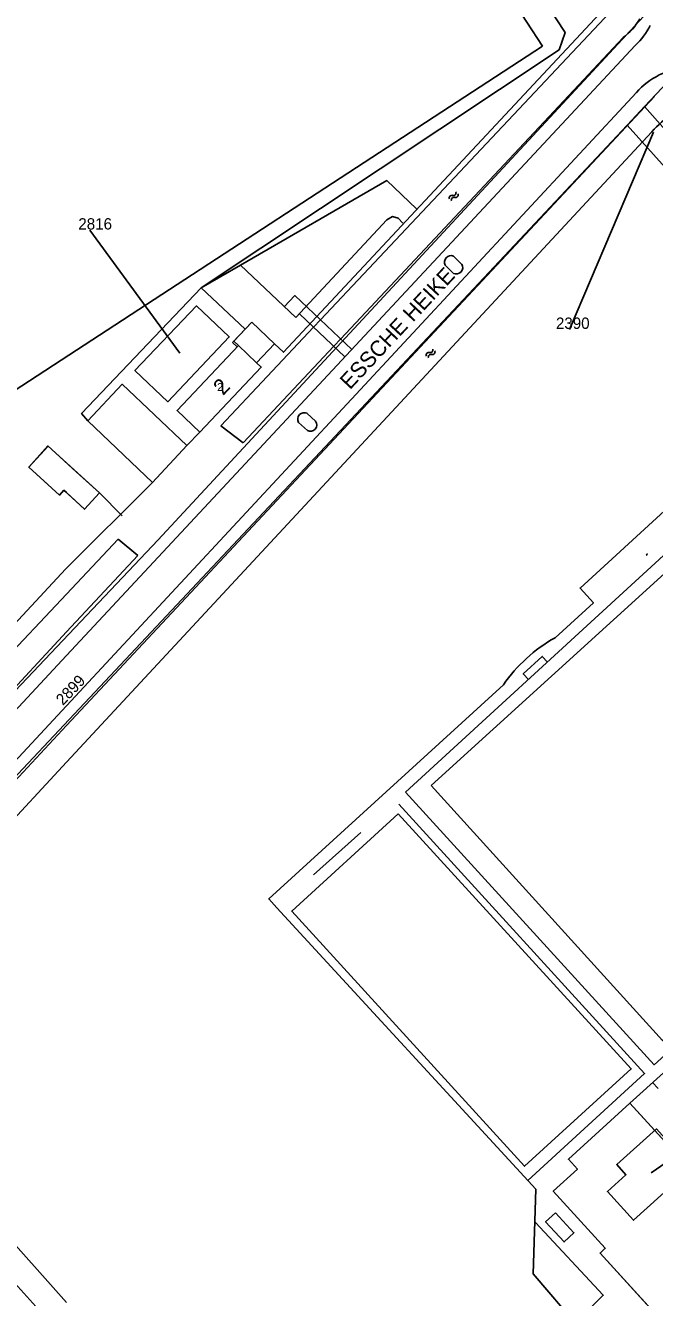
# Model space of a CAD drawing. Extents: x 148816 to 151297, y 399515 to 402500.
# Drawn here: x 149493.5 to 149593.5, y 401012.1 to 401214.2 of the extents above; entities that cross this region are included whole.
import ezdxf

# ---------------------------------------------------------------- set-up
doc = ezdxf.new("R2010")
doc.units = 0
for name, color, linetype in [('B01 Hoofdgebouw  [T] Norm', 7, 'Continuous'), ('B01 hoofgebouw', 7, 'Continuous'), ('B02 Bijgebouw  [D] Norm', 7, 'Continuous'), ('B03 Overig opstal  [D] Norm', 7, 'Continuous'), ('B03 Overig opstal  [T] Norm', 7, 'Continuous'), ('G01 perceelsgrens', 7, 'Continuous'), ('S02 Open verharding  Norm', 7, 'Continuous'), ('S05 Water  Norm', 7, 'Continuous'), ('T03 Hek raster  [D] Gem', 7, 'Continuous'), ('T03 Hek raster  [T] Norm', 7, 'Continuous'), ('T04 Haag heg  [D] Gem', 7, 'Continuous'), ('T09 Insteek water  [T] Norm', 7, 'Continuous'), ('T10 Cultuurscheiding  [T] Gem', 7, 'Continuous'), ('V00 Kant verharding algemeen  [T] Norm', 7, 'Continuous'), ('V00 Kant verharding algemeen secundair  [T] Gem', 7, 'Continuous'), ('Z01 perceelnummer', 7, 'Continuous'), ('Z02 huisnummer', 7, 'Continuous'), ('Z02 Huisnummer  [Tekst] Norm', 7, 'Continuous'), ('Z06 straatnaam', 7, 'Continuous')]:
    doc.layers.add(name, color=color, linetype=linetype)

msp = doc.modelspace()

# ---------------------------------------------------------------- linework, layer by layer
at = {"layer": 'B01 Hoofdgebouw  [T] Norm'}
for p, q in [((149510.87, 401159.36), (149520.65, 401169.63)), ((149520.65, 401169.63), (149525.85, 401164.7)), ((149525.85, 401164.7), (149516.11, 401154.4)), ((149517.57, 401153.03), (149527.31, 401163.33)), ((149527.31, 401163.33), (149530.21, 401160.58)), ((149516.11, 401154.4), (149510.87, 401159.36)), ((149530.94, 401159.89), (149521.2, 401149.59)), ((149530.21, 401160.58), (149530.94, 401159.89)), ((149503.37, 401151.34), (149508.83, 401157.18)), ((149508.83, 401157.18), (149519.14, 401147.42)), ((149521.2, 401149.59), (149517.57, 401153.03)), ((149513.64, 401141.57), (149503.37, 401151.34)), ((149505.23, 401139.91), (149497.07, 401147.36)), ((149519.14, 401147.42), (149513.64, 401141.57)), ((149494.02, 401144), (149498.88, 401139.58)), ((149498.88, 401139.58), (149499.58, 401140.35)), ((149499.58, 401140.35), (149500, 401139.96)), ((149500, 401139.96), (149502.86, 401137.31)), ((149502.86, 401137.31), (149505.23, 401139.91)), ((149589.53, 401042.97), (149579.77, 401034.06)), ((149599.61, 401031.96), (149589.53, 401042.97)), ((149579.77, 401034.06), (149581.2, 401032.49)), ((149581.2, 401032.49), (149577.36, 401028.99)), ((149577.36, 401028.99), (149585.63, 401019.93)), ((149585.63, 401019.93), (149584.79, 401019.16)), ((149584.79, 401019.16), (149601.71, 401000.62))]:
    msp.add_line(p, q, dxfattribs=at)
at = {"layer": 'B01 hoofgebouw'}
for points in [[(149516.11, 401154.4), (149525.85, 401164.7), (149520.65, 401169.63), (149510.87, 401159.36), (149516.11, 401154.4)], [(149521.2, 401149.59), (149530.94, 401159.89), (149530.21, 401160.58), (149533.06, 401163.58), (149529.43, 401167.03)], [(149529.43, 401167.03), (149526.58, 401164.02), (149527.31, 401163.33)], [(149527.31, 401163.33), (149517.57, 401153.03), (149521.2, 401149.59)], [(149519.14, 401147.42), (149508.83, 401157.18), (149503.37, 401151.34), (149513.64, 401141.57), (149519.14, 401147.42)], [(149501.54, 401143.28), (149497.04, 401147.37), (149493.99, 401144.02), (149495.18, 401142.94)], [(149495.18, 401142.94), (149498.88, 401139.58), (149499.58, 401140.35), (149502.86, 401137.31), (149505.23, 401139.91), (149501.54, 401143.28)], [(149589.53, 401042.97), (149599.61, 401031.96), (149599.21, 401031.59), (149607.21, 401022.85), (149605.26, 401020.99), (149613.8, 401011.58), (149601.71, 401000.62), (149584.79, 401019.16), (149585.63, 401019.93), (149577.36, 401028.99), (149581.2, 401032.49), (149579.77, 401034.06), (149589.53, 401042.97)]]:
    msp.add_lwpolyline(points, dxfattribs=at)
at = {"layer": 'B02 Bijgebouw  [D] Norm'}
msp.add_lwpolyline([(149577.69, 401025.57), (149580.64, 401022.39), (149579.08, 401020.95), (149576.13, 401024.12)], close=True, dxfattribs=at)
at = {"layer": 'B03 Overig opstal  [D] Norm'}
for p, q in [((149526.39, 401163.82), (149529.43, 401167.03)), ((149529.43, 401167.03), (149533.06, 401163.58)), ((149527.12, 401163.13), (149526.39, 401163.82)), ((149533.06, 401163.58), (149530.21, 401160.58)), ((149497.07, 401147.36), (149494.02, 401144))]:
    msp.add_line(p, q, dxfattribs=at)
at = {"layer": 'B03 Overig opstal  [T] Norm'}
msp.add_lwpolyline([(149576.42, 401113.04), (149575.62, 401113.93), (149572.59, 401111.16), (149573.4, 401110.27)], dxfattribs=at)
at = {"layer": 'G01 perceelsgrens'}
for points in [[(149399.91, 401011.52), (149514.57, 401132.44), (149592.39, 401216.34)], [(149591.88, 401201.27), (149599.29, 401209.15), (149755.87, 401012.23)], [(149589.13, 401198.34), (149595.14, 401191.62), (149598.13, 401194.27), (149591.88, 401201.27)], [(149589.13, 401198.34), (149591.88, 401201.27)], [(149402.74, 401000), (149589.13, 401198.34)], [(149525.85, 401164.7), (149520.65, 401169.63), (149510.87, 401159.36), (149516.11, 401154.4), (149525.85, 401164.7)], [(149599.35, 401032.72), (149590.11, 401024.37), (149585.96, 401028.96), (149588.9, 401031.61), (149587.46, 401033.21), (149593.76, 401038.9), (149599.35, 401032.72)]]:
    msp.add_lwpolyline(points, dxfattribs=at)
at = {"layer": 'S02 Open verharding  Norm'}
for p, q in [((149592.3, 401130.24), (149592.12, 401130.09)), ((149592.13, 401130.1), (149592.17, 401130.06)), ((149592.33, 401130.19), (149592.15, 401130.05)), ((149592.17, 401130.13), (149592.16, 401130.15)), ((149592.21, 401130.08), (149592.2, 401130.09)), ((149592.24, 401130.12), (149592.21, 401130.17)), ((149592.25, 401130.2), (149592.24, 401130.21)), ((149592.28, 401130.23), (149592.32, 401130.18)), ((149592.29, 401130.14), (149592.28, 401130.15))]:
    msp.add_line(p, q, dxfattribs=at)
at = {"layer": 'S05 Water  Norm'}
for centre, start, end in [((149561.25, 401186.76), 74.5688, 198.4238), ((149561.48, 401187.58), 254.5688, 18.4238), ((149561.81, 401187.27), 254.5688, 18.4238), ((149561.58, 401186.45), 74.5688, 198.4238), ((149557.59, 401161.8), 75.1719, 199.0269), ((149557.92, 401161.49), 75.1719, 199.0269), ((149557.81, 401162.62), 255.1719, 19.0269), ((149558.14, 401162.32), 255.1719, 19.0269)]:
    msp.add_arc(centre, 0.425, start, end, dxfattribs=at)
at = {"layer": 'T03 Hek raster  [D] Gem'}
for p, q in [((149505.23, 401139.91), (149508.85, 401136.3)), ((149434.89, 401058.6), (149499.85, 401127.78))]:
    msp.add_line(p, q, dxfattribs=at)
msp.add_lwpolyline([(149513.64, 401141.57), (149499.85, 401127.78)], dxfattribs=at)
at = {"layer": 'T03 Hek raster  [T] Norm'}
for p, q in [((149533.43, 401074.03), (149574.59, 401029.31)), ((149574.59, 401029.31), (149574.17, 401015.89)), ((149574.17, 401015.89), (149587.77, 401000))]:
    msp.add_line(p, q, dxfattribs=at)
for points in [[(149530.91, 401286.83), (149586.98, 401218.5), (149534.46, 401162.26), (149533.06, 401163.58)], [(149553.89, 401092.38), (149626.89, 401159.32), (149666.76, 401115.63), (149593.38, 401049.07), (149553.87, 401092.38)], [(149600.87, 401138.21), (149597.74, 401135.37), (149595.69, 401137.63), (149581.62, 401124.79), (149583.73, 401122.45), (149577.64, 401116.9)], [(149569.43, 401109.42), (149532.14, 401075.43), (149533.43, 401074.03)], [(149552.83, 401090.46), (149591.88, 401047.67), (149573.29, 401030.72)], [(149539.25, 401079.23), (149546.78, 401085.96)]]:
    msp.add_lwpolyline(points, dxfattribs=at)
msp.add_arc((149589.54, 401095.61), 24.39, 119.1893, 145.5031, dxfattribs=at)
at = {"layer": 'T04 Haag heg  [D] Gem'}
msp.add_lwpolyline([(149521.2, 401149.59), (149519.14, 401147.42)], dxfattribs=at)
at = {"layer": 'T09 Insteek water  [T] Norm'}
for p, q in [((149587.19, 401217.12), (149540.36, 401167.41)), ((149543.57, 401164.37), (149588.45, 401212.23)), ((149593.46, 401202.87), (149500, 401102.96)), ((149500, 401097.12), (149593.02, 401197.28)), ((149540.36, 401167.41), (149539.27, 401166.24)), ((149539.27, 401166.24), (149524.52, 401150.59)), ((149528.08, 401147.85), (149542.48, 401163.2)), ((149542.48, 401163.2), (149543.57, 401164.37)), ((149524.52, 401150.59), (149528.08, 401147.85)), ((149508.2, 401132.56), (149500, 401123.85)), ((149511.31, 401129.97), (149508.2, 401132.56)), ((149500, 401117.83), (149511.31, 401129.97)), ((149500, 401123.85), (149429.13, 401048.61)), ((149432.44, 401045.28), (149500, 401117.83)), ((149500, 401102.96), (149458.84, 401058.96)), ((149461.86, 401056.05), (149500, 401097.12))]:
    msp.add_line(p, q, dxfattribs=at)
for centre, radius, start, end in [((149582.48, 401220.19), 9.95, 306.8718, 330.0279), ((149608.69, 401182.81), 21.33, 125.6144, 137.2796)]:
    msp.add_arc(centre, radius, start, end, dxfattribs=at)
at = {"layer": 'T10 Cultuurscheiding  [T] Gem'}
for points in [[(149575.63, 401210.86), (149491.68, 401156.15), (149456.85, 401209.61), (149540.79, 401264.31)], [(149557.93, 401093.45), (149625.74, 401155.03), (149662.54, 401114.51), (149594.74, 401052.92)], [(149552.73, 401088.96), (149589.75, 401048.43), (149572.81, 401032.95), (149535.79, 401073.48)]]:
    msp.add_lwpolyline(points, close=True, dxfattribs=at)
msp.add_lwpolyline([(149554.86, 401250.09), (149579.24, 401213.04), (149578.3, 401210.3), (149521.37, 401172.47)], dxfattribs=at)
at = {"layer": 'V00 Kant verharding algemeen  [T] Norm'}
for p, q in [((149500, 401114.1), (149590.4, 401211)), ((149500, 401106.1), (149590.58, 401203.51)), ((149536.43, 401167.76), (149527.64, 401176.09)), ((149521.37, 401172.47), (149528.39, 401165.93)), ((149544.24, 401161.53), (149537.01, 401168.38)), ((149393.56, 401000), (149500, 401114.1)), ((149458.12, 401061.07), (149500, 401106.1)), ((149500, 401005.26), (149454.71, 401055.48)), ((149500, 401011.3), (149461.81, 401054.16)), ((149594.02, 401045.29), (149593.15, 401046.26))]:
    msp.add_line(p, q, dxfattribs=at)
for points in [[(149503.37, 401151.34), (149502.38, 401152.52), (149521.37, 401172.47), (149527.64, 401176.09)], [(149545.34, 401162.7), (149536.29, 401171.27), (149534.61, 401169.49)], [(149589.54, 401043), (149609.85, 401061.29), (149610.71, 401060.32), (149614.88, 401063.98), (149613.97, 401064.94)], [(149574.51, 401024.04), (149585.3, 401012.47), (149580.96, 401008.15)]]:
    msp.add_lwpolyline(points, dxfattribs=at)
for centre, radius, start, end in [((149582.49, 401219.38), 11.53, 313.3304, 333.1035), ((149599.36, 401195.85), 11.65, 93.6041, 138.898)]:
    msp.add_arc(centre, radius, start, end, dxfattribs=at)
at = {"layer": 'V00 Kant verharding algemeen secundair  [T] Gem'}
for p, q in [((149561.51, 401177.53), (149562.83, 401176.22)), ((149560.19, 401176.08), (149561.48, 401174.79)), ((149536.86, 401151.11), (149538.28, 401149.81)), ((149538.25, 401152.55), (149539.59, 401151.32))]:
    msp.add_line(p, q, dxfattribs=at)
for points in [[(149527.64, 401176.09), (149550.92, 401189.52), (149555.6, 401185.03)], [(149553.46, 401182.77), (149552.7, 401183.56), (149551.81, 401183.81), (149550.92, 401183.28), (149536.43, 401167.76)]]:
    msp.add_lwpolyline(points, dxfattribs=at)
for centre, radius, start, end in [((149561.11, 401176.57), 1.04, 67.3068, 208.1458), ((149561.94, 401175.71), 1.03, 243.3576, 30.0517), ((149537.78, 401151.62), 1.05, 63.3574, 208.6656), ((149538.76, 401150.72), 1.02, 242.2739, 35.8568)]:
    msp.add_arc(centre, radius, start, end, dxfattribs=at)
at = {"layer": 'Z01 perceelnummer'}
for points in [[(149579.94, 401165.87), (149593.3, 401197.21)], [(149503.7, 401181.65), (149518.02, 401162.12)], [(149632.6, 401059.26), (149592.93, 401031.9)]]:
    msp.add_lwpolyline(points, dxfattribs=at)

# ---------------------------------------------------------------- texts
for s, p in [('2816', (149501.87, 401181.75)), ('2390', (149577.78, 401165.97))]:
    msp.add_text(s, height=1.8, dxfattribs=at).set_placement(p)
msp.add_text('2899', height=1.8, rotation=46.1875, dxfattribs=at).set_placement((149499.42, 401106.07))
at = {"layer": 'Z02 huisnummer'}
msp.add_text('2', height=2.5, rotation=46.6204, dxfattribs=at).set_placement((149524.88, 401155.3))
at = {"layer": 'Z02 Huisnummer  [Tekst] Norm'}
msp.add_text('2', height=1.25, dxfattribs=at).set_placement((149523.93, 401156.11))
at = {"layer": 'Z06 straatnaam'}
msp.add_text('ESSCHE HEIKE', height=2.5, rotation=46.9861, dxfattribs=at).set_placement((149545.04, 401156.21))

doc.saveas('drawing.dxf')
